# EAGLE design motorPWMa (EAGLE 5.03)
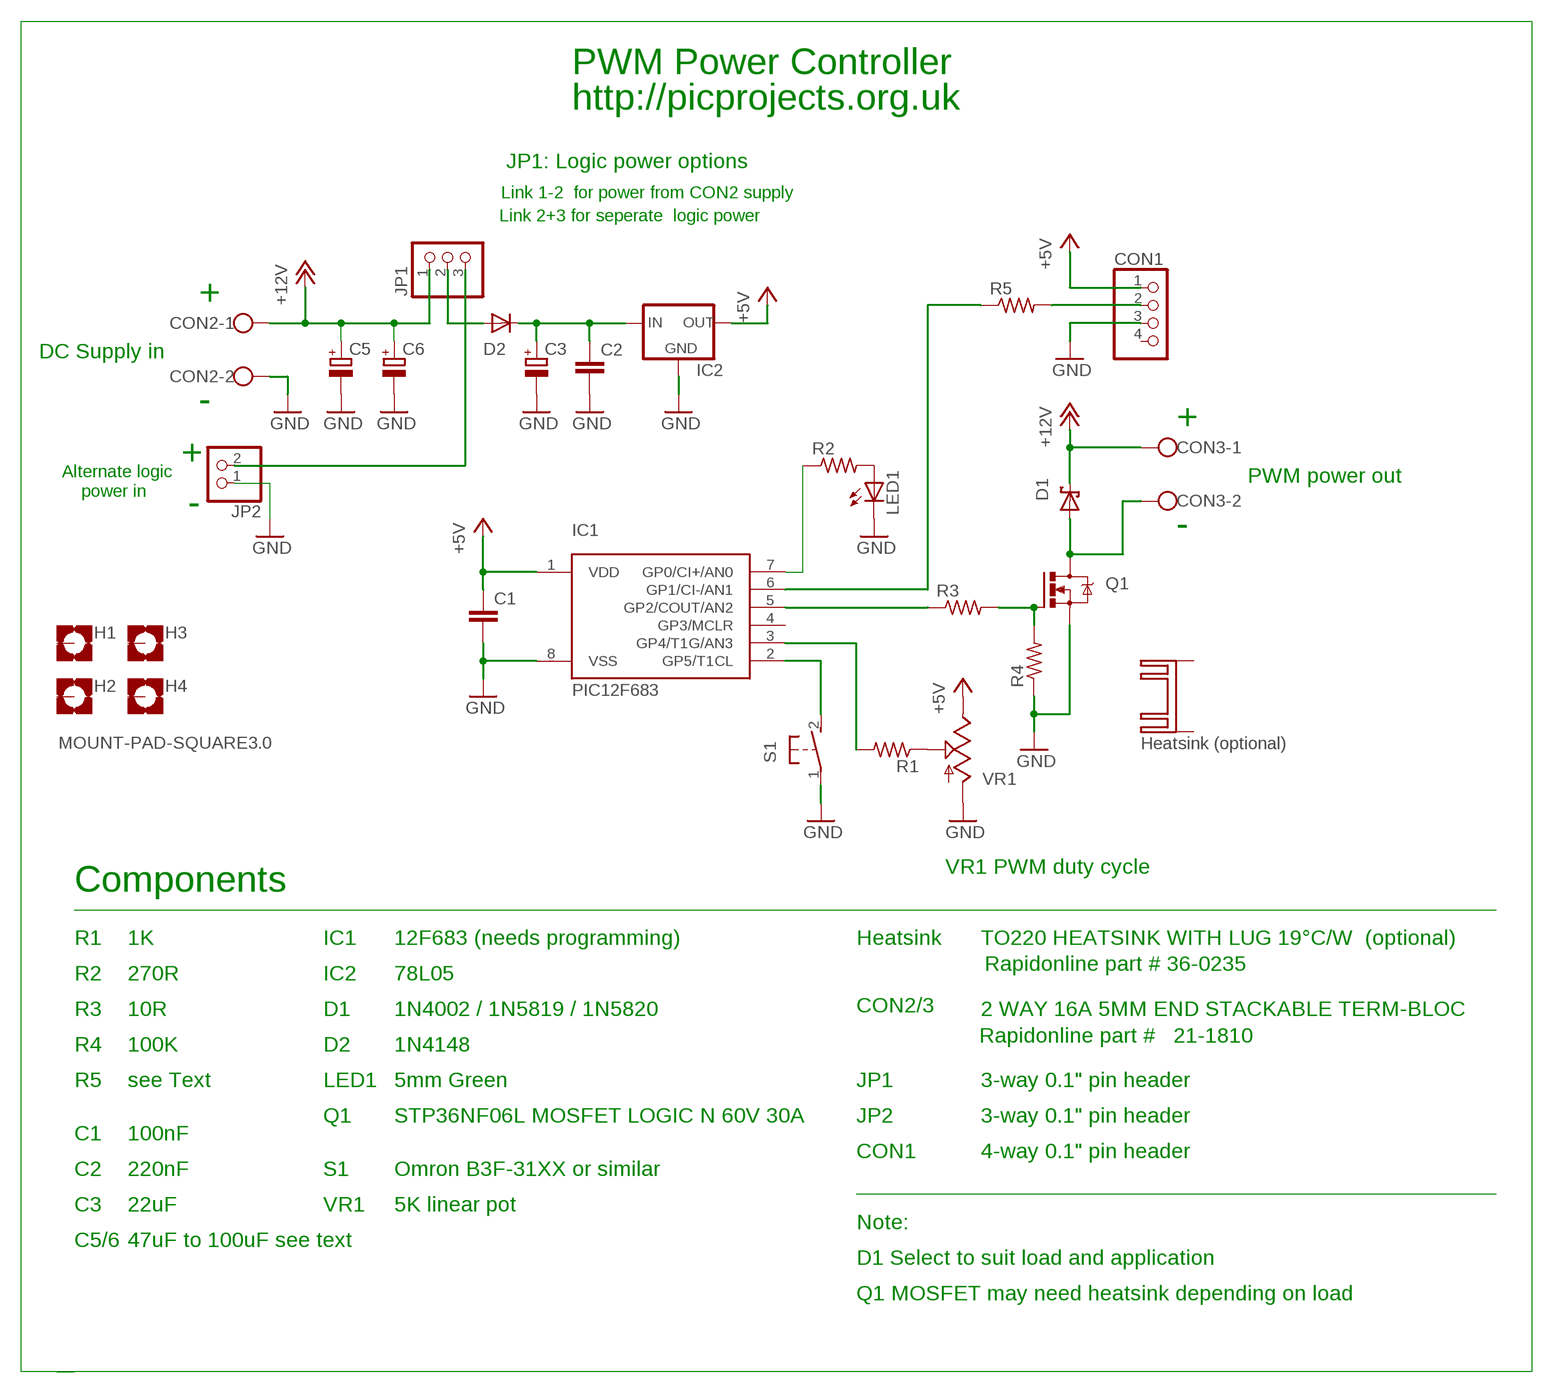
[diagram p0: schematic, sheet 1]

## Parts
C1  C-EU050-030X075  [C050-030X075]
C2  C-EU050-030X075  [C050-030X075]
C3  CPOL-EUE2.5-5  [E2,5-5]
C5  CPOL-EUE2.5-5  [E2,5-5]
C6  CPOL-EUE2.5-5  [E2,5-5]
CON1  PINHD-1X4  [1X04]
CON2  W237-02P  [W237-132]
CON3  W237-02P  [W237-132]
D1  1N5908  [C4111-15]
D2  1N4148  [DO35-10]
H1  MOUNT-PAD-SQUARE3.0  [3,0-PAD-SQUARE]
H2  MOUNT-PAD-SQUARE3.0  [3,0-PAD-SQUARE]
H3  MOUNT-PAD-SQUARE3.0  [3,0-PAD-SQUARE]
H4  MOUNT-PAD-SQUARE3.0  [3,0-PAD-SQUARE]
IC1  PIC12F683  PIC12F629P  [DIL8]
IC2  78LXX  [78LXX]
JP1  PINHD-1X3  [1X03]
JP2  PINHD-1X2  [1X02]
KK2  FK222  [FK222]
LED1  LED5MM  [LED5MM]
Q1  IRF740  [TO220BV]
R1  R-US_0207/10  [0207/10]
R2  R-US_0207/10  [0207/10]
R3  R-US_0207/10  [0207/10]
R4  R-US_0207/10  [0207/10]
R5  R-US_0207/10  [0207/10]
S1  31-XX  [B3F-31XX]
VR1  TRIM_US-CIP20C-6MM  [CIP20C-6MM]

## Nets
+5V: C1.1 CON1.1 IC1.1(VDD) IC2.OUT VR1.E
+12V [Power]: C5.+ C6.+ CON2.1 CON3.1 D1.C JP1.1
GND [Power]: C1.2 C2.2 C3.- C5.- C6.- CON1.3 CON2.2 IC1.8(VSS) IC2.GND JP2.1 LED1.K(C) Q1.S R4.1 S1.1(P) VR1.A
N$1: IC1.7(GP0/CI+/AN0) R2.1
N$2: LED1.A R2.2
N$3: R1.1 VR1.S
N$4: IC1.3(GP4/T1G/AN3) R1.2
N$5: IC1.5(GP2/COUT/AN2) R3.1
N$6: Q1.G R3.2 R4.2
N$7 [Power]: CON3.2 D1.A Q1.D
N$8: IC1.2(GP5/T1CL) S1.2(S)
N$9 [Power]: C2.1 C3.+ D2.C IC2.IN
N$10: CON1.2 R5.2
N$11: IC1.6(GP1/CI-/AN1) R5.1
N$12: D2.A JP1.2
N$17: JP1.3 JP2.2
Unconnected: CON1.4 H1.B3,0(MOUNT) H2.B3,0(MOUNT) H3.B3,0(MOUNT) H4.B3,0(MOUNT) IC1.4(GP3/MCLR) KK2.A2,8(K) KK2.B2,8(K)

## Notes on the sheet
- PWM Power Controller
- http://picprojects.org.uk
- JP1: Logic power options
- Link 1-2  for power from CON2 supply
- Link 2+3 for seperate  logic power
- +
- DC Supply in
- -
- +
- +
- Alternate logic
- PWM power out
- power in
- -
- -
- Heatsink (optional)
- VR1 PWM duty cycle
- Components
- R1 | 1K | IC1 | 12F683 (needs programming) | Heatsink | TO220 HEATSINK WITH LUG 19°C/W  (optional)
- Rapidonline part # 36-0235
- R2 | 270R | IC2 | 78L05
- R3 | 10R | D1 | 1N4002 / 1N5819 / 1N5820 | CON2/3 | 2 WAY 16A 5MM END STACKABLE TERM-BLOC
- Rapidonline part #   21-1810
- R4 | 100K | D2 | 1N4148
- R5 | see Text | LED1 | 5mm Green | JP1 | 3-way 0.1" pin header
- Q1 | STP36NF06L MOSFET LOGIC N 60V 30A | JP2 | 3-way 0.1" pin header
- C1 | 100nF
- CON1 | 4-way 0.1" pin header
- C2 | 220nF | S1 | Omron B3F-31XX or similar
- C3 | 22uF | VR1 | 5K linear pot
- Note:
- C5/6 | 47uF to 100uF see text
- D1 Select to suit load and application
- Q1 MOSFET may need heatsink depending on load

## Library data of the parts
C1 C2 = rcl:C-EU: CAPACITOR, European symbol
C3 C5 C6 = rcl:CPOL-EU: POLARIZED CAPACITOR, European symbol
CON1 = pinhead:PINHD-1X4: PIN HEADER
CON2 CON3 = con-wago-508:W237-02P: WAGO SREW CLAMP
D1 = diode:1N5908: DIODE
D2 = diode:1N4148: DIODE
H1-H4 = holes:MOUNT-PAD-SQUARE: MOUNTING PAD, square
IC1 = microchip-5:PIC12F6*: uPC nW 1k Program Flash memory 2x Timer Comparator 10b A/D converter/ 4xIN
IC2 = v-reg:78LXX: VOLTAGE REGULATOR
JP1 = pinhead:PINHD-1X3: PIN HEADER
JP2 = pinhead:PINHD-1X2: PIN HEADER
KK2 = heatsink:FK222: HEATSINK
LED1 = led:LED: LED
Q1 = transistor-power:IRF740: N-CHANNEL MOS FET
R1-R5 = rcl:R-US_: RESISTOR, American symbol
S1 = switch-omron:31-XX: OMRON SWITCH
VR1 = pot:TRIM_US-: POTENTIOMETER

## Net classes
0 default: width 0.61 mm
1 Power: width 1.27 mm

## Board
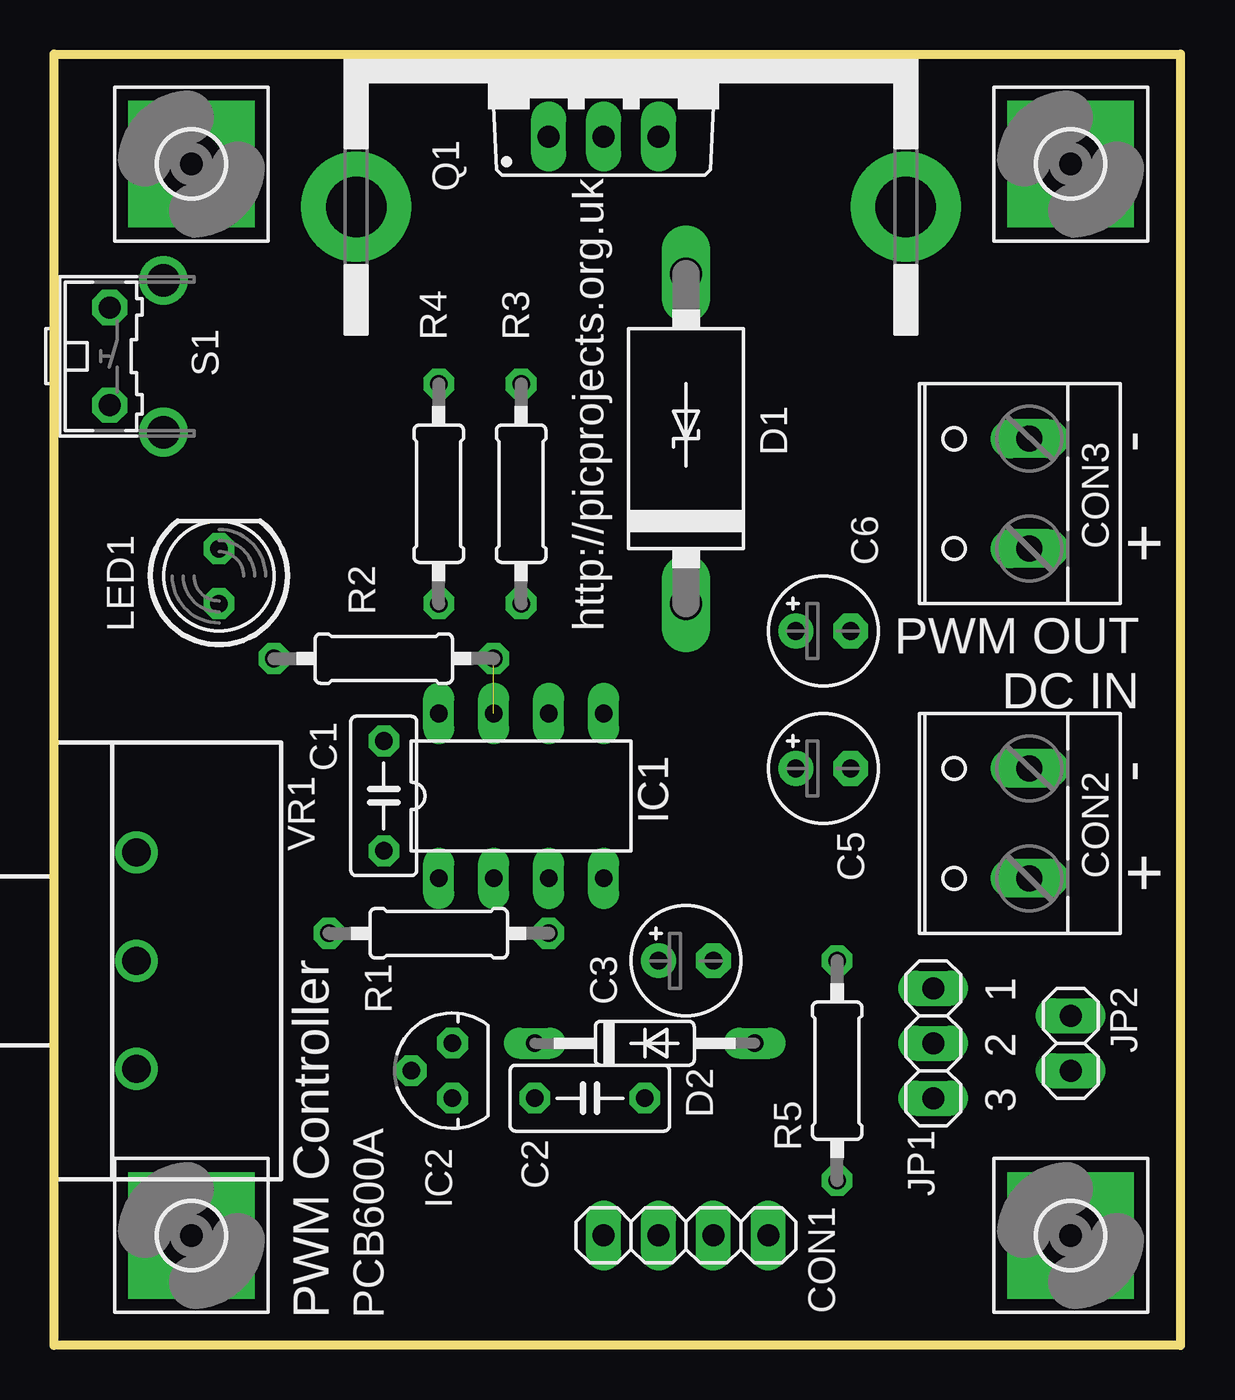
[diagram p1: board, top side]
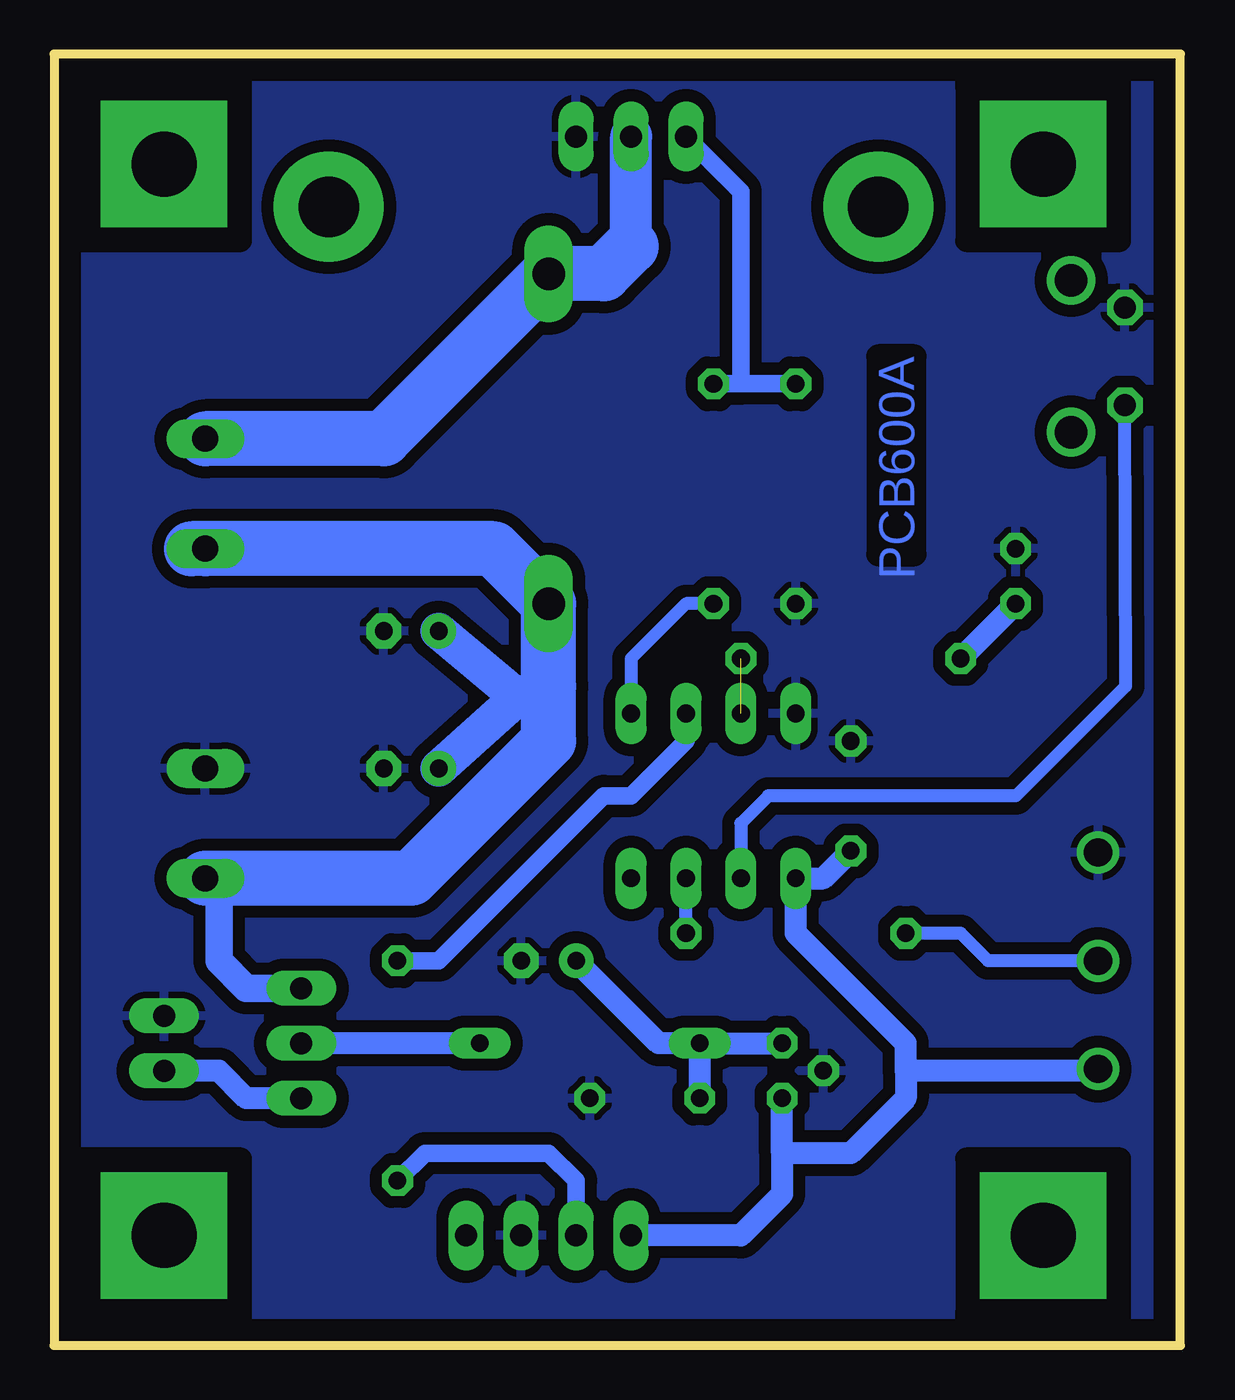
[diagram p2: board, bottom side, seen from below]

Size 52.07 x 59.69 mm. Coordinates in mm from the lower left corner, seen from the top.
Outline: 0,0 0,59.69 52.07,59.69 52.07,0 0,0
Copper layers (1*16): Top 0.035mm / dielectric 1.5mm / Bottom 0.035mm
Design rules "default *": minimum track width 10mil, minimum drill 24mil, track to track 22mil, track to pad 20mil, pad to pad 8mil, via to via 8mil, smd to smd 8mil, copper to edge 40mil, drill to drill 8mil, minimum pad ring 12mil, minimum via ring 8mil, stop-mask expansion 4mil, vias tented up to drill 0mil, thermal gap 12mil

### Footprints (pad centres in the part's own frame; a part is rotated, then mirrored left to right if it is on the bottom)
C050-030X075 = drill 0.813 octagon: 1 -2.54,0; 2 2.54,0
E2,5-5 = drill 0.813 pad 1.6 round: + -1.27,0 | drill 0.813 pad 1.6 octagon: - 1.27,0
1X04 = drill 1.016 long: 1 -3.81,0; 2 -1.27,0; 3 1.27,0; 4 3.81,0
W237-132 = drill 1.194 long: 1 -2.54,-0.635; 2 2.54,-0.635
C4111-15 = drill 1.499 long: A 7.62,0; C -7.62,0
DO35-10 = drill 0.813 long: A 5.08,0; C -5.08,0
3,0-PAD-SQUARE = drill 3 pad 5.842 square: B3,0 0,0
DIL8 = drill 0.813 long: 1 -3.81,-3.81; 2 -1.27,-3.81; 3 1.27,-3.81; 4 3.81,-3.81; 5 3.81,3.81; 6 1.27,3.81; 7 -1.27,3.81; 8 -3.81,3.81
78LXX = drill 0.813 octagon: GND 0,1.905; IN 1.27,0; OUT -1.27,0
1X03 = drill 1.016 long: 1 -2.54,0; 2 0,0; 3 2.54,0
1X02 = drill 1.016 long: 1 -1.27,0; 2 1.27,0
FK222 = drill 2.794 pad 5.08 round: A2,8 5.791,-12.7; B2,8 5.791,12.7
LED5MM = drill 0.813 octagon: A -1.27,0; K 1.27,0
TO220BV = drill 1.016 long: D 0,-2.54; G -2.54,-2.54; S 2.54,-2.54
0207/10 = drill 0.813 octagon: 1 -5.08,0; 2 5.08,0
B3F-31XX = drill 1.016 octagon: 1 -2.261,-1.245; 2 2.261,-1.245 | drill 1.499 pad 2.159 round: 3 -3.505,1.245; 4 3.505,1.245
CIP20C-6MM = drill 1.3 pad 1.93 round: A -5,0; E 5,0; S 0,0

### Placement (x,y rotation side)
C1  15.24,25.4 90 top
C2  24.77,11.43 0 top
C3  29.21,17.78 0 top
C5  35.56,26.67 0 top
C6  35.56,33.02 0 top
CON1  29.21,5.08 0 top
CON2  44.45,24.13 90 top
CON3  44.45,39.37 90 top
D1  29.21,41.91 90 top
D2  27.3,13.97 0 top
H1  46.99,5.08 90 top
H2  6.35,54.61 90 top
H3  46.99,54.61 90 top
H4  6.35,5.08 90 top
IC1  21.59,25.4 0 top
IC2  18.41,12.7 90 top
JP1  40.64,13.97 270 top
JP2  46.99,13.97 270 top
KK2  26.67,58.42 270 top
LED1  7.62,35.56 90 top
Q1  25.4,58.42 0 top
R1  17.78,19.05 0 top
R2  15.24,31.75 180 top
R3  21.59,39.37 90 top
R4  17.78,39.37 90 top
R5  36.2,12.7 270 top
S1  3.81,45.72 270 top
VR1  3.81,17.78 270 top

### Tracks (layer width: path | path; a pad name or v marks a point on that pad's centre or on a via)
+5V
  Bottom 0.61: VR1.E 3.81,12.7
  Bottom 1.016: C1.1 16.51,21.59 IC1.1 17.78,19.05 12.7,13.97 12.7,12.7 | CON1.1 20.32,5.08 18.41,6.98 18.41,8.89 | 18.41,8.89 IC2.OUT | 18.41,8.89 15.24,8.89 12.7,11.43 12.7,12.7 | 3.81,12.7 12.7,12.7
+12V
  Bottom 1.016: 30.9,29.71 32.17,28.79 30.48,30.48 29.21,30.48
  Bottom 1.27: JP1.1 43.18,16.51 44.45,17.78 44.45,21.59 | 35.56,21.59 36.2,22.23
  Bottom 1.676: C5.+ 30.9,29.71 30.48,29.84 C6.+
  Bottom 2.54: CON2.1 44.45,21.59 35.56,21.59 29.21,27.94 29.21,30.48 D1.C 31.75,36.83 CON3.1 45.72,36.83
GND
  pour Bottom: 0,0 0,58.42 52.07,58.42 52.07,0
N$1  (1 unrouted)
N$2
  Bottom 1.016: LED1.A R2.2
N$3
  Bottom 0.61: R1.1 10.16,19.05 8.89,17.78 VR1.S
N$4
  Bottom 0.61: R1.2 IC1.3
N$5
  Bottom 0.61: IC1.5 25.4,31.75 22.86,34.29 R3.1
N$6
  Bottom 0.813: R4.2 R3.2 20.32,44.45 20.32,53.34 Q1.G
N$7
  Bottom 1.93: 25.4,50.8 Q1.D
  Bottom 2.54: CON3.2 36.83,41.91 D1.A 26.67,49.53 25.4,50.8
N$8
  Bottom 0.61: 15.24,25.4 19.05,25.4 20.32,24.13 IC1.2 | 15.24,25.4 16.51,25.4 | 15.24,25.4 7.62,25.4 2.54,30.48 S1.2
N$9
  Bottom 1.016: C3.+ 24.13,13.97 D2.C | C2.1 D2.C | D2.C IC2.IN
  Bottom 1.27: D2.C 21.59,13.97
N$10
  Bottom 0.813: CON1.2 27.94,7.62 29.21,8.89 34.93,8.89 R5.2
N$11
  Bottom 0.813: IC1.6 22.86,27.94 25.4,25.4 26.67,25.4 34.29,17.78 R5.1
N$12
  Bottom 1.016: D2.A JP1.2
N$17
  Bottom 1.016: JP2.2 44.45,12.7 43.18,11.43 JP1.3

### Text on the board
Bottom: PCB600A
tPlace: - | + | PWM OUT | http://picprojects.org.uk | DC IN | - | + | 1 | 2 | 3 | PWM Controller | PCB600A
